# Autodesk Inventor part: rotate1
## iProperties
Author: Administrator
Created: 2000-12
Part Number: rotate1
Document SubType Name: Modeling
Designer: Administrator
Control State: 0
Master: False
Checked Out: False
PropertySet Name: Design Tracking Control
Shininess: 0.0
PropertySet Name: _Private Model Information
Density: 0.0
Volumn: 0.0
Area: 0.0
PropertySet Name: Model Information
